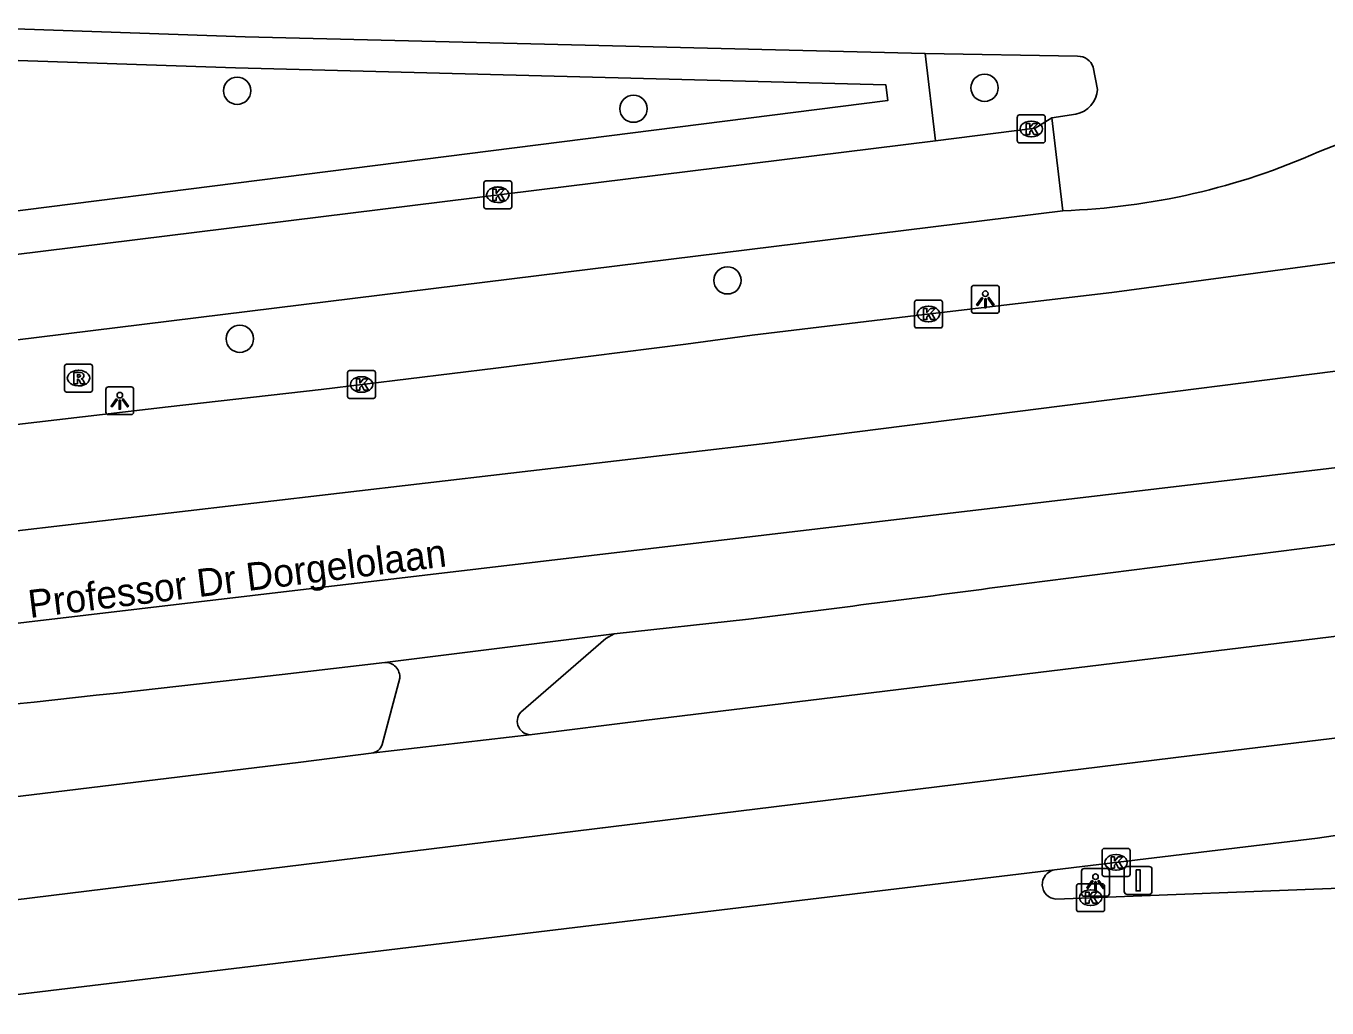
# Model space of a CAD drawing. Extents: x 161477 to 163040, y 383680 to 384868.
# Drawn here: x 161726.48 to 161773.12, y 383998.77 to 384033.98 of the extents above; entities that cross this region are included whole.
import ezdxf

# ---------------------------------------------------------------- set-up
doc = ezdxf.new("R2010")
doc.units = 0
for name, color, linetype in [('IMGEO_Boom', 7, 'Continuous'), ('IMGEO_Fietspad_gesloten', 7, 'Continuous'), ('IMGEO_Fietspad_open', 7, 'Continuous'), ('IMGEO_Kolk', 7, 'Continuous'), ('IMGEO_Lichtpunt', 7, 'Continuous'), ('IMGEO_Openbare_ruimte_label', 7, 'Continuous'), ('IMGEO_Rijbaan_lokaal_gesloten', 7, 'Continuous'), ('IMGEO_Rioolput', 7, 'Continuous'), ('IMGEO_Verkeersbordpaal', 7, 'Continuous'), ('IMGEO_Voetpad_gesloten', 7, 'Continuous'), ('IMGEO_Voetpad_open', 7, 'Continuous')]:
    doc.layers.add(name, color=color, linetype=linetype)

msp = doc.modelspace()

# ---------------------------------------------------------------- linework, layer by layer
at = {"layer": 'IMGEO_Boom'}
for centre in [(161760.849, 384031.771), (161734.053, 384031.665), (161748.259, 384031.02), (161751.627, 384024.864), (161734.149, 384022.771)]:
    msp.add_circle(centre, 0.489, dxfattribs=at)
at = {"layer": 'IMGEO_Fietspad_gesloten'}
for points in [[(161700.668, 384034.787), (161717.726, 384034.171), (161718.177, 384034.155), (161734.34, 384033.599), (161758.72, 384033.003)], [(161758.72, 384033.003), (161764.181, 384032.902)], [(161764.743, 384032.509), (161764.894, 384031.713)], [(161772.816, 384029.47), (161778.226, 384031.584)], [(161764.121, 384030.82), (161763.253, 384030.692)], [(161763.253, 384030.692), (161763.653, 384027.361)]]:
    msp.add_lwpolyline(points, dxfattribs=at)
for centre, radius, start, end in [((161764.199, 384032.329), 0.573, 18.2927, 91.778), ((161763.916, 384031.779), 0.981, 282.0858, 356.1539), ((161762.802, 384052.019), 24.673, 271.9772, 293.9463)]:
    msp.add_arc(centre, radius, start, end, dxfattribs=at)
at = {"layer": 'IMGEO_Fietspad_open'}
for points in [[(161759.087, 384029.863), (161762.659, 384030.32), (161763.253, 384030.692)], [(161693.678, 384021.946), (161694.128, 384021.966), (161699.157, 384022.191), (161702.143, 384022.584), (161705.045, 384023.188), (161759.087, 384029.863)], [(161763.653, 384027.361), (161706.222, 384020.27), (161703.259, 384019.694)]]:
    msp.add_lwpolyline(points, dxfattribs=at)
at = {"layer": 'IMGEO_Kolk'}
for p, q in [((161762.096, 384030.795), (161762.948, 384030.795)), ((161762.021, 384029.869), (161762.021, 384030.721)), ((161762.509, 384030.575), (161762.534, 384030.575)), ((161763.022, 384030.721), (161763.022, 384029.869)), ((161762.532, 384030.015), (161762.507, 384030.015)), ((161762.948, 384029.795), (161762.096, 384029.795)), ((161742.896, 384027.506), (161742.896, 384028.358)), ((161742.971, 384028.432), (161743.823, 384028.432)), ((161743.384, 384028.212), (161743.409, 384028.212)), ((161743.897, 384028.358), (161743.897, 384027.506)), ((161743.407, 384027.652), (161743.382, 384027.652)), ((161743.823, 384027.432), (161742.971, 384027.432)), ((161758.336, 384023.231), (161758.336, 384024.083)), ((161758.411, 384024.157), (161759.263, 384024.157)), ((161758.824, 384023.937), (161758.849, 384023.937)), ((161759.337, 384024.083), (161759.337, 384023.231)), ((161758.847, 384023.377), (161758.822, 384023.377)), ((161759.263, 384023.157), (161758.411, 384023.157)), ((161738.01, 384020.704), (161738.01, 384021.556)), ((161738.085, 384021.63), (161738.937, 384021.63)), ((161739.011, 384021.556), (161739.011, 384020.704)), ((161738.498, 384021.41), (161738.523, 384021.41)), ((161738.937, 384020.63), (161738.085, 384020.63)), ((161738.521, 384020.85), (161738.496, 384020.85)), ((161765.06, 384003.565), (161765.06, 384004.417)), ((161765.135, 384004.491), (161765.987, 384004.491)), ((161765.548, 384004.271), (161765.573, 384004.271)), ((161766.061, 384004.417), (161766.061, 384003.565)), ((161765.987, 384003.491), (161765.135, 384003.491)), ((161765.571, 384003.711), (161765.546, 384003.711)), ((161764.147, 384002.3), (161764.147, 384003.152)), ((161764.222, 384003.226), (161765.074, 384003.226)), ((161764.635, 384003.006), (161764.66, 384003.006)), ((161765.148, 384003.152), (161765.148, 384002.3)), ((161764.658, 384002.446), (161764.633, 384002.446)), ((161765.074, 384002.226), (161764.222, 384002.226))]:
    msp.add_line(p, q, dxfattribs=at)
for points in [[(161762.096, 384030.795), (161762.948, 384030.795)], [(161762.021, 384029.869), (161762.021, 384030.721)], [(161762.342, 384030.495), (161762.465, 384030.495), (161762.465, 384030.344), (161762.595, 384030.495), (161762.759, 384030.495), (161762.613, 384030.344), (161762.766, 384030.095), (161762.614, 384030.095), (161762.529, 384030.259), (161762.465, 384030.192), (161762.465, 384030.095), (161762.342, 384030.095), (161762.342, 384030.495)], [(161763.022, 384030.721), (161763.022, 384029.869)], [(161762.948, 384029.795), (161762.096, 384029.795)], [(161742.896, 384027.506), (161742.896, 384028.358)], [(161742.971, 384028.432), (161743.823, 384028.432)], [(161743.217, 384028.132), (161743.34, 384028.132), (161743.34, 384027.981), (161743.47, 384028.132), (161743.634, 384028.132), (161743.488, 384027.981), (161743.641, 384027.732), (161743.489, 384027.732), (161743.404, 384027.896), (161743.34, 384027.829), (161743.34, 384027.732), (161743.217, 384027.732), (161743.217, 384028.132)], [(161743.897, 384028.358), (161743.897, 384027.506)], [(161743.823, 384027.432), (161742.971, 384027.432)], [(161758.336, 384023.231), (161758.336, 384024.083)], [(161758.411, 384024.157), (161759.263, 384024.157)], [(161758.657, 384023.857), (161758.78, 384023.857), (161758.78, 384023.706), (161758.91, 384023.857), (161759.074, 384023.857), (161758.928, 384023.706), (161759.081, 384023.457), (161758.929, 384023.457), (161758.844, 384023.621), (161758.78, 384023.554), (161758.78, 384023.457), (161758.657, 384023.457), (161758.657, 384023.857)], [(161759.337, 384024.083), (161759.337, 384023.231)], [(161759.263, 384023.157), (161758.411, 384023.157)], [(161738.01, 384020.704), (161738.01, 384021.556)], [(161738.085, 384021.63), (161738.937, 384021.63)], [(161739.011, 384021.556), (161739.011, 384020.704)], [(161738.331, 384021.33), (161738.454, 384021.33), (161738.454, 384021.179), (161738.584, 384021.33), (161738.748, 384021.33), (161738.602, 384021.179), (161738.755, 384020.93), (161738.603, 384020.93), (161738.518, 384021.094), (161738.454, 384021.027), (161738.454, 384020.93), (161738.331, 384020.93), (161738.331, 384021.33)], [(161738.937, 384020.63), (161738.085, 384020.63)], [(161765.06, 384003.565), (161765.06, 384004.417)], [(161765.135, 384004.491), (161765.987, 384004.491)], [(161766.061, 384004.417), (161766.061, 384003.565)], [(161765.381, 384004.191), (161765.504, 384004.191), (161765.504, 384004.04), (161765.634, 384004.191), (161765.798, 384004.191), (161765.652, 384004.04), (161765.805, 384003.791), (161765.653, 384003.791), (161765.568, 384003.955), (161765.504, 384003.888), (161765.504, 384003.791), (161765.381, 384003.791), (161765.381, 384004.191)], [(161765.987, 384003.491), (161765.135, 384003.491)], [(161764.147, 384002.3), (161764.147, 384003.152)], [(161764.222, 384003.226), (161765.074, 384003.226)], [(161764.468, 384002.926), (161764.591, 384002.926), (161764.591, 384002.775), (161764.721, 384002.926), (161764.885, 384002.926), (161764.739, 384002.775), (161764.892, 384002.526), (161764.74, 384002.526), (161764.655, 384002.69), (161764.591, 384002.623), (161764.591, 384002.526), (161764.468, 384002.526), (161764.468, 384002.926)], [(161765.148, 384003.152), (161765.148, 384002.3)], [(161765.074, 384002.226), (161764.222, 384002.226)]]:
    msp.add_lwpolyline(points, dxfattribs=at)
for centre, start, end in [((161762.098, 384030.719), 91.552, 178.448), ((161762.098, 384030.719), 91.552, 178.448), ((161762.946, 384030.719), 1.552, 88.448), ((161762.946, 384030.719), 1.552, 88.448), ((161762.098, 384029.871), 181.552, 268.448), ((161762.098, 384029.871), 181.552, 268.448), ((161762.946, 384029.871), 271.552, 358.448), ((161762.946, 384029.871), 271.552, 358.448), ((161742.973, 384028.356), 91.552, 178.448), ((161742.973, 384028.356), 91.552, 178.448), ((161743.821, 384028.356), 1.552, 88.448), ((161743.821, 384028.356), 1.552, 88.448), ((161742.973, 384027.508), 181.552, 268.448), ((161742.973, 384027.508), 181.552, 268.448), ((161743.821, 384027.508), 271.552, 358.448), ((161743.821, 384027.508), 271.552, 358.448), ((161758.413, 384024.081), 91.552, 178.448), ((161758.413, 384024.081), 91.552, 178.448), ((161759.261, 384024.081), 1.552, 88.448), ((161759.261, 384024.081), 1.552, 88.448), ((161758.413, 384023.233), 181.552, 268.448), ((161758.413, 384023.233), 181.552, 268.448), ((161759.261, 384023.233), 271.552, 358.448), ((161759.261, 384023.233), 271.552, 358.448), ((161738.087, 384021.554), 91.552, 178.448), ((161738.087, 384021.554), 91.552, 178.448), ((161738.935, 384021.554), 1.552, 88.448), ((161738.935, 384021.554), 1.552, 88.448), ((161738.087, 384020.706), 181.552, 268.448), ((161738.087, 384020.706), 181.552, 268.448), ((161738.935, 384020.706), 271.552, 358.448), ((161738.935, 384020.706), 271.552, 358.448), ((161765.137, 384004.415), 91.552, 178.448), ((161765.137, 384004.415), 91.552, 178.448), ((161765.985, 384004.415), 1.552, 88.448), ((161765.985, 384004.415), 1.552, 88.448), ((161765.137, 384003.567), 181.552, 268.448), ((161765.137, 384003.567), 181.552, 268.448), ((161765.985, 384003.567), 271.552, 358.448), ((161765.985, 384003.567), 271.552, 358.448), ((161764.224, 384003.15), 91.552, 178.448), ((161764.224, 384003.15), 91.552, 178.448), ((161765.072, 384003.15), 1.552, 88.448), ((161765.072, 384003.15), 1.552, 88.448), ((161764.224, 384002.302), 181.552, 268.448), ((161764.224, 384002.302), 181.552, 268.448), ((161765.072, 384002.302), 271.552, 358.448), ((161765.072, 384002.302), 271.552, 358.448)]:
    msp.add_arc(centre, 0.0765, start, end, dxfattribs=at)
for centre, major_axis, ratio, start_param, end_param in [((161762.508, 384030.295), (-0.387, 0.002), 0.722429, 4.712389, 7.853982), ((161762.533, 384030.295), (-0.39, 0.002), 0.717154, 1.570796, 4.712389), ((161743.383, 384027.932), (-0.387, 0.002), 0.722429, 4.712389, 7.853982), ((161743.408, 384027.932), (-0.39, 0.002), 0.717154, 1.570796, 4.712389), ((161758.823, 384023.657), (-0.387, 0.002), 0.722429, 4.712389, 7.853982), ((161758.848, 384023.657), (-0.39, 0.002), 0.717154, 1.570796, 4.712389), ((161738.497, 384021.13), (-0.387, 0.002), 0.722429, 4.712389, 7.853982), ((161738.522, 384021.13), (-0.39, 0.002), 0.717154, 1.570796, 4.712389), ((161765.547, 384003.991), (-0.387, 0.002), 0.722429, 4.712389, 7.853982), ((161765.572, 384003.991), (-0.39, 0.002), 0.717154, 1.570796, 4.712389), ((161764.634, 384002.726), (-0.387, 0.002), 0.722429, 4.712389, 7.853982), ((161764.659, 384002.726), (-0.39, 0.002), 0.717154, 1.570796, 4.712389)]:
    msp.add_ellipse(centre, major_axis=major_axis, ratio=ratio, start_param=start_param, end_param=end_param, dxfattribs=at)
at = {"layer": 'IMGEO_Lichtpunt'}
for p, q in [((161760.376, 384024.587), (161760.376, 384023.78)), ((161760.376, 384024.587), (161760.376, 384023.78)), ((161761.278, 384024.682), (161760.47, 384024.682)), ((161761.278, 384024.682), (161760.47, 384024.682)), ((161761.372, 384023.78), (161761.372, 384024.587)), ((161761.372, 384023.78), (161761.372, 384024.587)), ((161760.47, 384023.686), (161761.278, 384023.686)), ((161760.47, 384023.686), (161761.278, 384023.686)), ((161730.247, 384021.045), (161729.439, 384021.045)), ((161730.247, 384021.045), (161729.439, 384021.045)), ((161729.345, 384020.95), (161729.345, 384020.143)), ((161729.345, 384020.95), (161729.345, 384020.143)), ((161730.341, 384020.143), (161730.341, 384020.95)), ((161730.341, 384020.143), (161730.341, 384020.95)), ((161729.439, 384020.049), (161730.247, 384020.049)), ((161729.439, 384020.049), (161730.247, 384020.049)), ((161765.226, 384003.774), (161764.418, 384003.774)), ((161765.226, 384003.774), (161764.418, 384003.774)), ((161764.324, 384003.679), (161764.324, 384002.872)), ((161764.324, 384003.679), (161764.324, 384002.872)), ((161765.32, 384002.872), (161765.32, 384003.679)), ((161765.32, 384002.872), (161765.32, 384003.679)), ((161764.418, 384002.778), (161765.226, 384002.778)), ((161764.418, 384002.778), (161765.226, 384002.778))]:
    msp.add_line(p, q, dxfattribs=at)
for points in [[(161760.75, 384024.251), (161760.789, 384024.223), (161760.601, 384023.961), (161760.563, 384023.988), (161760.75, 384024.251)], [(161760.852, 384024.203), (161760.899, 384024.203), (161760.899, 384023.881), (161760.852, 384023.881), (161760.852, 384024.203)], [(161760.962, 384024.223), (161761, 384024.25), (161761.187, 384023.988), (161761.148, 384023.96), (161760.962, 384024.223)], [(161729.719, 384020.614), (161729.758, 384020.586), (161729.57, 384020.324), (161729.532, 384020.351), (161729.719, 384020.614)], [(161729.821, 384020.566), (161729.868, 384020.566), (161729.868, 384020.244), (161729.821, 384020.244), (161729.821, 384020.566)], [(161729.931, 384020.586), (161729.969, 384020.613), (161730.156, 384020.351), (161730.117, 384020.323), (161729.931, 384020.586)], [(161764.698, 384003.343), (161764.737, 384003.315), (161764.549, 384003.053), (161764.511, 384003.08), (161764.698, 384003.343)], [(161764.8, 384003.295), (161764.847, 384003.295), (161764.847, 384002.973), (161764.8, 384002.973), (161764.8, 384003.295)], [(161764.91, 384003.315), (161764.948, 384003.342), (161765.135, 384003.08), (161765.096, 384003.052), (161764.91, 384003.315)]]:
    msp.add_lwpolyline(points, dxfattribs=at)
for centre in [(161760.875, 384024.385), (161729.844, 384020.748), (161764.823, 384003.477)]:
    msp.add_circle(centre, 0.0994, dxfattribs=at)
for centre, start, end in [((161760.47, 384024.587), 90, 180), ((161760.47, 384024.587), 90, 180), ((161761.278, 384024.587), 0, 90), ((161761.278, 384024.587), 0, 90), ((161760.47, 384023.78), 180, 270), ((161760.47, 384023.78), 180, 270), ((161761.278, 384023.78), 270, 0), ((161761.278, 384023.78), 270, 360), ((161729.439, 384020.95), 90, 180), ((161729.439, 384020.95), 90, 180), ((161730.247, 384020.95), 0, 90), ((161730.247, 384020.95), 0, 90), ((161729.439, 384020.143), 180, 270), ((161729.439, 384020.143), 180, 270), ((161730.247, 384020.143), 270, 0), ((161730.247, 384020.143), 270, 360), ((161764.418, 384003.679), 90, 180), ((161764.418, 384003.679), 90, 180), ((161765.226, 384003.679), 0, 90), ((161765.226, 384003.679), 0, 90), ((161764.418, 384002.872), 180, 270), ((161764.418, 384002.872), 180, 270), ((161765.226, 384002.872), 270, 0), ((161765.226, 384002.872), 270, 360)]:
    msp.add_arc(centre, 0.0946, start, end, dxfattribs=at)
at = {"layer": 'IMGEO_Rijbaan_lokaal_gesloten'}
for points in [[(162246.408, 384079.189), (162227.626, 384076.889), (162181.187, 384071.188), (162137.796, 384065.987), (162093.056, 384060.636), (162050.016, 384055.235), (162024.421, 384052.135), (162005.138, 384049.833), (161993.828, 384048.483), (161960.735, 384044.482), (161945.288, 384042.532), (161917.195, 384039.231), (161895.749, 384036.581), (161871.905, 384033.68), (161827.864, 384028.429), (161795.621, 384024.429), (161753.08, 384019.028), (161721.837, 384015.377), (161706.74, 384013.577), (161696.893, 384013.027), (161694.855, 384012.926)], [(161696.618, 383999.076), (161717.081, 384001.544), (161768.879, 384007.897), (161825.477, 384014.75), (161917.35, 384025.954), (162007.495, 384037.033), (162008.923, 384037.209), (162102.422, 384048.613), (162177.172, 384057.667), (162248.391, 384066.39)], [(161846.778, 384034.306), (161838.36, 384033.362), (161830.293, 384032.344), (161823.202, 384031.479), (161813.278, 384030.282), (161808.93, 384029.766), (161803.723, 384029.183), (161802.176, 384029.078), (161796.662, 384028.308), (161789.811, 384027.457), (161780.934, 384026.394), (161773.852, 384025.569), (161765.407, 384024.434), (161758.694, 384023.638), (161752.521, 384022.902), (161750.139, 384022.575), (161743.325, 384021.716), (161737.062, 384020.952), (161731.582, 384020.326), (161722.153, 384019.231), (161718.096, 384018.853)], [(161955.645, 384034.342), (161947.767, 384033.359), (161941.167, 384032.594), (161932.884, 384031.511), (161926.538, 384030.732), (161918.49, 384029.795), (161912.208, 384029.026), (161904.739, 384028.152), (161898.618, 384027.408), (161892.7, 384026.697), (161887.995, 384026.183), (161881.096, 384025.303), (161875.103, 384024.611), (161868.493, 384023.755), (161862.148, 384023.025), (161854.166, 384022.062), (161823.343, 384018.177), (161748.637, 384009.081), (161744.626, 384008.574)], [(161695.269, 384009.746), (161701.12, 384010.023), (161710.519, 384010.823), (161724.566, 384012.374), (161779.16, 384018.826), (161800.208, 384021.201)], [(161785.86, 384017.048), (161784.178, 384016.769), (161761.603, 384013.896)], [(161865.049, 384016.046), (161854.527, 384014.894), (161850.706, 384014.47), (161849.74, 384014.259), (161842.62, 384013.413), (161835.35, 384012.513), (161828.807, 384011.75), (161811.276, 384009.575), (161802.199, 384008.506), (161794.62, 384007.571), (161787.004, 384006.583), (161786.031, 384006.552), (161779.357, 384005.838), (161772.777, 384004.866), (161763.35, 384003.723)], [(161752.379, 384012.714), (161747.565, 384012.187)], [(161739.341, 384011.163), (161747.565, 384012.187)], [(161739.341, 384011.163), (161735.662, 384010.732)], [(161744.626, 384008.574), (161738.86, 384007.907)], [(161738.86, 384007.907), (161736.335, 384007.586), (161696.412, 384002.75), (161696.191, 384002.723)], [(161697.015, 383995.692), (161711.954, 383997.541), (161763.35, 384003.723)], [(161763.406, 384002.679), (161774.505, 384003.101)]]:
    msp.add_lwpolyline(points, dxfattribs=at)
for centre, radius, start, end in [((161586.568, 385343.237), 1340.815, 277.10362, 277.501004), ((161606.132, 385135.008), 1131.713, 275.364128, 276.572189), ((161763.443, 384003.204), 0.527, 100.1705, 265.9703)]:
    msp.add_arc(centre, radius, start, end, dxfattribs=at)
at = {"layer": 'IMGEO_Rioolput'}
for p, q in [((161727.863, 384020.932), (161727.863, 384021.784)), ((161727.938, 384021.858), (161728.79, 384021.858)), ((161728.351, 384021.638), (161728.376, 384021.638)), ((161728.864, 384021.784), (161728.864, 384020.932)), ((161728.374, 384021.078), (161728.349, 384021.078)), ((161728.79, 384020.858), (161727.938, 384020.858))]:
    msp.add_line(p, q, dxfattribs=at)
for points in [[(161727.863, 384020.932), (161727.863, 384021.784)], [(161727.938, 384021.858), (161728.79, 384021.858)], [(161728.452, 384021.556), (161728.2, 384021.558), (161728.2, 384021.158)], [(161728.378, 384021.477), (161728.324, 384021.477), (161728.324, 384021.396)], [(161728.864, 384021.784), (161728.864, 384020.932)], [(161728.2, 384021.158), (161728.324, 384021.158), (161728.324, 384021.32), (161728.335, 384021.32)], [(161728.324, 384021.396), (161728.376, 384021.396)], [(161728.382, 384021.291), (161728.453, 384021.158), (161728.593, 384021.158), (161728.528, 384021.284)], [(161728.79, 384020.858), (161727.938, 384020.858)]]:
    msp.add_lwpolyline(points, dxfattribs=at)
for centre, radius, start, end in [((161727.94, 384021.782), 0.0765, 91.552, 178.448), ((161727.94, 384021.782), 0.0765, 91.552, 178.448), ((161728.384, 384021.381), 0.0964, 77.0061, 93.1865), ((161728.398, 384021.438), 0.0378, 276.6634, 79.6772), ((161728.451, 384021.446), 0.109, 350.3612, 89.416), ((161728.788, 384021.782), 0.0765, 1.552, 88.448), ((161728.788, 384021.782), 0.0765, 1.552, 88.448), ((161728.334, 384021.267), 0.0533, 26.0293, 88.6989), ((161728.36, 384021.585), 0.19, 274.7715, 282.9687), ((161728.449, 384021.446), 0.112, 277.5842, 350.9817), ((161728.433, 384021.231), 0.108, 29.5134, 73.7905), ((161727.94, 384020.934), 0.0765, 181.552, 268.448), ((161727.94, 384020.934), 0.0765, 181.552, 268.448), ((161728.788, 384020.934), 0.0765, 271.552, 358.448), ((161728.788, 384020.934), 0.0765, 271.552, 358.448)]:
    msp.add_arc(centre, radius, start, end, dxfattribs=at)
for centre, major_axis, ratio, start_param, end_param in [((161728.35, 384021.358), (-0.387, 0.002), 0.722429, 4.712389, 7.853982), ((161728.375, 384021.358), (-0.39, 0.002), 0.717154, 1.570796, 4.712389)]:
    msp.add_ellipse(centre, major_axis=major_axis, ratio=ratio, start_param=start_param, end_param=end_param, dxfattribs=at)
at = {"layer": 'IMGEO_Verkeersbordpaal'}
for p, q in [((161765.857, 384002.946), (161765.857, 384003.746)), ((161765.857, 384003.746), (161765.857, 384002.946)), ((161765.957, 384003.846), (161766.747, 384003.846)), ((161766.747, 384003.846), (161765.957, 384003.846)), ((161766.847, 384003.746), (161766.847, 384002.946)), ((161766.847, 384002.946), (161766.847, 384003.746)), ((161766.747, 384002.846), (161765.957, 384002.846)), ((161765.957, 384002.846), (161766.747, 384002.846))]:
    msp.add_line(p, q, dxfattribs=at)
msp.add_lwpolyline([(161766.277, 384003.721), (161766.427, 384003.721), (161766.427, 384002.971), (161766.277, 384002.971), (161766.277, 384003.721)], dxfattribs=at)
for centre, start, end in [((161765.957, 384003.746), 90, 180), ((161765.957, 384003.746), 90, 180), ((161766.747, 384003.746), 0, 90), ((161766.747, 384003.746), 360, 90), ((161765.957, 384002.946), 180, 270), ((161765.957, 384002.946), 180, 270), ((161766.747, 384002.946), 270, 0), ((161766.747, 384002.946), 270, 0)]:
    msp.add_arc(centre, 0.1, start, end, dxfattribs=at)
at = {"layer": 'IMGEO_Voetpad_gesloten'}
for points in [[(161747.565, 384012.187), (161747.265, 384012.019), (161744.223, 384009.381)], [(161739.256, 384008.22), (161739.881, 384010.593)]]:
    msp.add_lwpolyline(points, dxfattribs=at)
for centre, radius, start, end in [((161739.357, 384010.638), 0.526, 355.1239, 91.7798), ((161744.576, 384009.053), 0.482, 137.1227, 275.9506), ((161738.801, 384008.388), 0.485, 276.9717, 339.6743)]:
    msp.add_arc(centre, radius, start, end, dxfattribs=at)
at = {"layer": 'IMGEO_Voetpad_open'}
for points in [[(161702.989, 384026.278), (161703.08, 384024.434), (161757.379, 384031.316), (161757.305, 384031.876), (161733.987, 384032.488), (161701.381, 384033.589)], [(161758.72, 384033.003), (161759.087, 384029.863)]]:
    msp.add_lwpolyline(points, dxfattribs=at)

# ---------------------------------------------------------------- texts
at = {"layer": 'IMGEO_Openbare_ruimte_label'}
msp.add_text('Professor Dr Dorgelolaan', height=1, rotation=7.0681, dxfattribs=at).set_placement((161726.622, 384012.754))

doc.saveas('drawing.dxf')
